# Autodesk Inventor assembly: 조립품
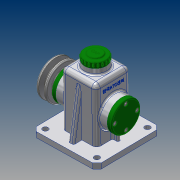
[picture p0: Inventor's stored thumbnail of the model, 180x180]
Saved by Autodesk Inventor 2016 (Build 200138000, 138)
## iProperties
Created: 2018-10
Part Number: 조립품
Material: 일반
Document SubType Name: Assembly
Designer: user
Author: user
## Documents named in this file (14)
- C:\Users\user\Desktop\481016V1013\조립품.iam
- C:\Users\user\Desktop\481016V1013\부품.ipt
- C:\Users\user\Desktop\481016V1013\베어링 15 x 35 x 11.ipt
- C:\Users\user\Desktop\481016V1013\축.ipt
- C:\Users\user\Desktop\481016V1013\멈춤링 15 x 1.ipt
- C:\Users\user\Desktop\481016V1013\뒤커버.ipt
- C:\Users\user\Desktop\481016V1013\앞커버.ipt
- C:\Users\user\Desktop\481016V1013\볼트 M4 x 10.ipt
- C:\Users\user\Desktop\481016V1013\상부캡.ipt
- C:\Users\user\Desktop\481016V1013\키 5 x 5 x 14.ipt
- C:\Users\user\Desktop\481016V1013\오일실 15 25 7.ipt
- C:\Users\user\Desktop\481016V1013\V-벨트풀리.ipt
- C:\Users\user\Desktop\481016V1013\와셔.ipt
- C:\Users\user\Desktop\481016V1013\볼트 M6 x 12.ipt
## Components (1 placed, 1 different names)
1. V-벨트풀리:1
